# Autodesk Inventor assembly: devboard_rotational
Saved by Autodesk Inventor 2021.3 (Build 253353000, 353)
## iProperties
Created: 2023-09
Part Number: devboard_rotational
Document SubType Name: Assembly
Designer: AdminForWorker
Title: devboard_rotational v2
Author: AdminForWorker
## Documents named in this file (3)
- z:\worker\convert-fusion-r04-cosv3\tmp\job-1\2400\output\files\b50e43e6-88dc-4ae4-8798-25d0c03346c5\947db9c8-0523-4001-a64a-357d43b0493c.iam
- z:\worker\convert-fusion-r04-cosv3\tmp\job-1\2400\output\files\b50e43e6-88dc-4ae4-8798-25d0c03346c5\Adafruit DS3502 STEMMA QT v1.iam
- z:\worker\convert-fusion-r04-cosv3\tmp\job-1\2400\output\files\b50e43e6-88dc-4ae4-8798-25d0c03346c5\Part16.ipt
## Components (2 placed, 2 different names)
1. Adafruit DS3502 STEMMA QT v1:2 [sub-assembly]
2. Part16
